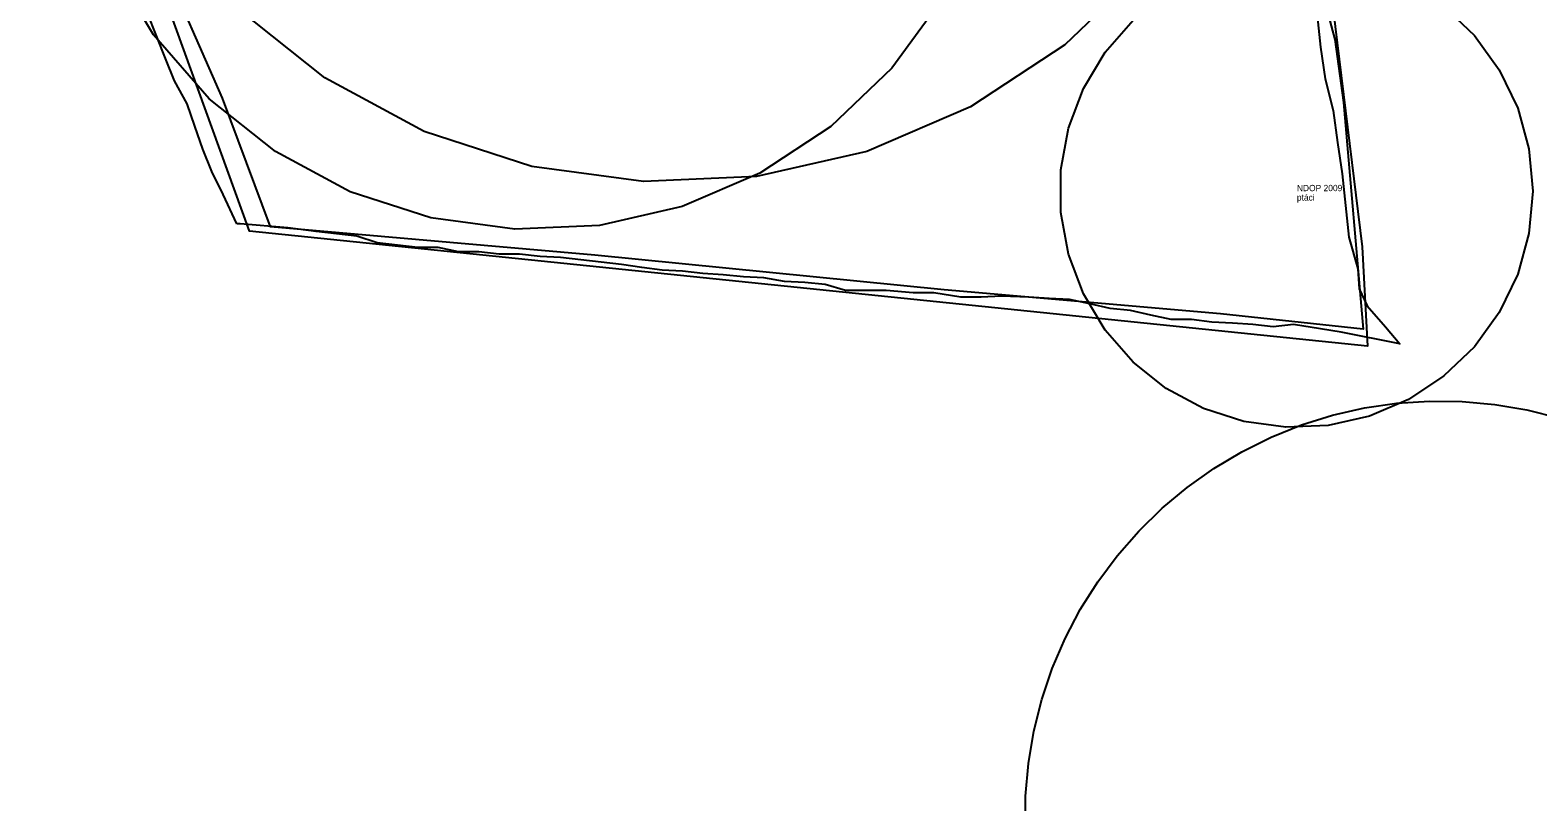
# Model space of a CAD drawing. Extents: x -477403 to -465463, y -1159182 to -1149227.
# Drawn here: x -468058.3 to -467579.9, y -1155339.7 to -1155094.9 of the extents above; entities that cross this region are included whole.
import ezdxf

# ---------------------------------------------------------------- set-up
doc = ezdxf.new("R2010")
doc.units = 0
for name, color, linetype in [('Vrstva 1', 7, 'Continuous'), ('Vrstva 10_stav', 7, 'Continuous'), ('Vrstva 2', 7, 'Continuous')]:
    doc.layers.add(name, color=color, linetype=linetype)

msp = doc.modelspace()

# ---------------------------------------------------------------- linework, layer by layer
at = {"layer": 'Vrstva 10_stav'}
msp.add_lwpolyline([(-468058.329, -1154963.054), (-467987.047, -1154964.711), (-467842.825, -1154968.027), (-467677.052, -1154987.919), (-467640.582, -1155007.812), (-467645.555, -1155082.41), (-467635.609, -1155163.639), (-467633.951, -1155195.135), (-467988.705, -1155158.665), (-468058.329, -1154966.369)], close=True, dxfattribs=at)
for points in [[(-467654.004, -1155061.965), (-467644.335, -1155097.878), (-467641.573, -1155117.906), (-467635.357, -1155189.731), (-467680.593, -1155184.897), (-467768.303, -1155177.3), (-467879.148, -1155166.25), (-467982.052, -1155157.272), (-467997.246, -1155116.525), (-468017.274, -1155070.943)], [(-467654.004, -1155061.965), (-467644.335, -1155097.878), (-467641.573, -1155117.906), (-467635.357, -1155189.731), (-467680.593, -1155184.897), (-467768.303, -1155177.3), (-467879.149, -1155166.25), (-467982.052, -1155157.272), (-467997.246, -1155116.525), (-468017.274, -1155070.943)], [(-467654.004, -1155061.965), (-467644.335, -1155097.878), (-467641.573, -1155117.906), (-467635.357, -1155189.731), (-467680.593, -1155184.897), (-467768.303, -1155177.3), (-467879.149, -1155166.25), (-467982.052, -1155157.272), (-467997.246, -1155116.525), (-468017.274, -1155070.943)], [(-467654.004, -1155061.965), (-467644.335, -1155097.878), (-467641.573, -1155117.906), (-467635.357, -1155189.731), (-467680.593, -1155184.897), (-467768.303, -1155177.3), (-467879.149, -1155166.25), (-467982.052, -1155157.272), (-467997.246, -1155116.525), (-468017.274, -1155070.943)], [(-467654.004, -1155061.965), (-467644.335, -1155097.878), (-467641.573, -1155117.906), (-467635.357, -1155189.731), (-467680.593, -1155184.897), (-467768.303, -1155177.3), (-467879.149, -1155166.25), (-467982.052, -1155157.272), (-467997.246, -1155116.525), (-468017.274, -1155070.943)], [(-467769.063, -1155085.175), (-467784.869, -1155106.931), (-467804.307, -1155125.515), (-467826.75, -1155140.329), (-467851.477, -1155150.898), (-467877.695, -1155156.882), (-467904.56, -1155158.089), (-467931.208, -1155154.479), (-467956.784, -1155146.169), (-467980.465, -1155133.426), (-468001.489, -1155116.659), (-468019.183, -1155096.408), (-468032.975, -1155073.323)], [(-467704.066, -1155074.745), (-467729.982, -1155099.523), (-467759.906, -1155119.276), (-467792.877, -1155133.368), (-467827.834, -1155141.347), (-467863.653, -1155142.955), (-467899.184, -1155138.142), (-467933.285, -1155127.062), (-467964.86, -1155110.071), (-467992.893, -1155087.716)], [(-467992.719, -1155156.375), (-467997.062, -1155147), (-468000.656, -1155139.75), (-468003.531, -1155132.625), (-468006.031, -1155125.375), (-468008.531, -1155118.25), (-468012.5, -1155111), (-468015.375, -1155103.875), (-468018.25, -1155096.75), (-468021.125, -1155089.5)], [(-467609.768, -1155087.353), (-467600.05, -1155096.645), (-467592.146, -1155107.523), (-467586.312, -1155119.637), (-467582.735, -1155132.598), (-467581.53, -1155145.99), (-467582.735, -1155159.382), (-467586.312, -1155172.343), (-467592.146, -1155184.457), (-467600.05, -1155195.335), (-467609.768, -1155204.627), (-467620.99, -1155212.035), (-467633.354, -1155217.319), (-467646.463, -1155220.311), (-467659.895, -1155220.914), (-467673.219, -1155219.11), (-467686.007, -1155214.955), (-467697.847, -1155208.583), (-467708.36, -1155200.2), (-467717.206, -1155190.074), (-467724.103, -1155178.531), (-467728.827, -1155165.943), (-467731.228, -1155152.713), (-467731.228, -1155139.267), (-467728.827, -1155126.037), (-467724.103, -1155113.449), (-467717.206, -1155101.906), (-467708.36, -1155091.78)], [(-467649.906, -1155090.25), (-467648.844, -1155100.25), (-467647.406, -1155110.375), (-467644.906, -1155120.375), (-467643.469, -1155130.5), (-467642.031, -1155140.5), (-467640.938, -1155150.5), (-467639.875, -1155160.625), (-467637, -1155170.625), (-467636.656, -1155177), (-467634.062, -1155182.375), (-467628.219, -1155189), (-467623.75, -1155194.375), (-467642.375, -1155190.75), (-467648.844, -1155189.625), (-467657.469, -1155188.25), (-467663.938, -1155189), (-467670.375, -1155188.25), (-467676.844, -1155187.875), (-467683.312, -1155187.5), (-467689.781, -1155186.75), (-467696.219, -1155186.75)], [(-467696.219, -1155186.75), (-467702.688, -1155185.375), (-467709.156, -1155183.875), (-467715.625, -1155183.25), (-467722.062, -1155181.75), (-467728.531, -1155180.375), (-467735, -1155180), (-467741.469, -1155179.625), (-467750.062, -1155179.25), (-467756.531, -1155179.625), (-467763, -1155179.625), (-467771.625, -1155178.25), (-467778.094, -1155178.25), (-467786.688, -1155177.5), (-467793.156, -1155177.5), (-467799.625, -1155177.5), (-467806.094, -1155175.625), (-467812.531, -1155175), (-467819, -1155174.625), (-467825.469, -1155173.5), (-467831.938, -1155173.125), (-467838.375, -1155172.5), (-467844.844, -1155172.125), (-467851.312, -1155171.375), (-467857.781, -1155171), (-467864.25, -1155170.25), (-467870.688, -1155169.25), (-467877.156, -1155168.5), (-467883.625, -1155167.75), (-467890.094, -1155167), (-467896.531, -1155166.75), (-467903, -1155166), (-467909.469, -1155166), (-467915.938, -1155165.25), (-467922.375, -1155165.25), (-467928.844, -1155163.875), (-467935.312, -1155163.875), (-467941.781, -1155163.125), (-467948.25, -1155162.375), (-467954.688, -1155160.25), (-467961.156, -1155159.5), (-467967.625, -1155158.75), (-467976.562, -1155157.625), (-467991.719, -1155156.375), (-467992.219, -1155156.375), (-467992.719, -1155156.375)], [(-467742.625, -1155348.274), (-467742.508, -1155337.905), (-467741.577, -1155327.577), (-467739.84, -1155317.355), (-467737.305, -1155307.3), (-467733.99, -1155297.475), (-467729.913, -1155287.94), (-467725.102, -1155278.755), (-467719.584, -1155269.975), (-467713.395, -1155261.655), (-467706.572, -1155253.847), (-467699.157, -1155246.598), (-467691.196, -1155239.953), (-467682.739, -1155233.954), (-467673.837, -1155228.636), (-467664.545, -1155224.033), (-467654.921, -1155220.173), (-467645.024, -1155217.081), (-467634.914, -1155214.774), (-467624.655, -1155213.268), (-467614.309, -1155212.571), (-467603.94, -1155212.688), (-467593.612, -1155213.619), (-467583.39, -1155215.356), (-467573.335, -1155217.891)]]:
    msp.add_lwpolyline(points, dxfattribs=at)

# ---------------------------------------------------------------- texts
at = {"layer": 'Vrstva 1'}
msp.add_text('ptáci', height=2, dxfattribs=at).set_placement((-467656.379, -1155148.99))
msp.add_text('ptáci', height=2, dxfattribs=at).set_placement((-467656.379, -1155148.99))
at = {"layer": 'Vrstva 2'}
msp.add_text('NDOP 2009', height=2, dxfattribs=at).set_placement((-467656.379, -1155145.99))
msp.add_text('NDOP 2009', height=2, dxfattribs=at).set_placement((-467656.379, -1155145.99))

doc.saveas('drawing.dxf')
